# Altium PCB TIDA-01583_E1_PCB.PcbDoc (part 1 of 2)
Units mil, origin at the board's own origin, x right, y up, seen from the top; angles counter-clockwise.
Board outline 2000 x 2400 mil, 4 copper layers (Top Layer, GND, PWR, Bottom Layer), stack 5.6 mil thick; 127 components, 58 nets, 301 pads, 119 vias.
Unrouted connection lines stored in the file: 16.
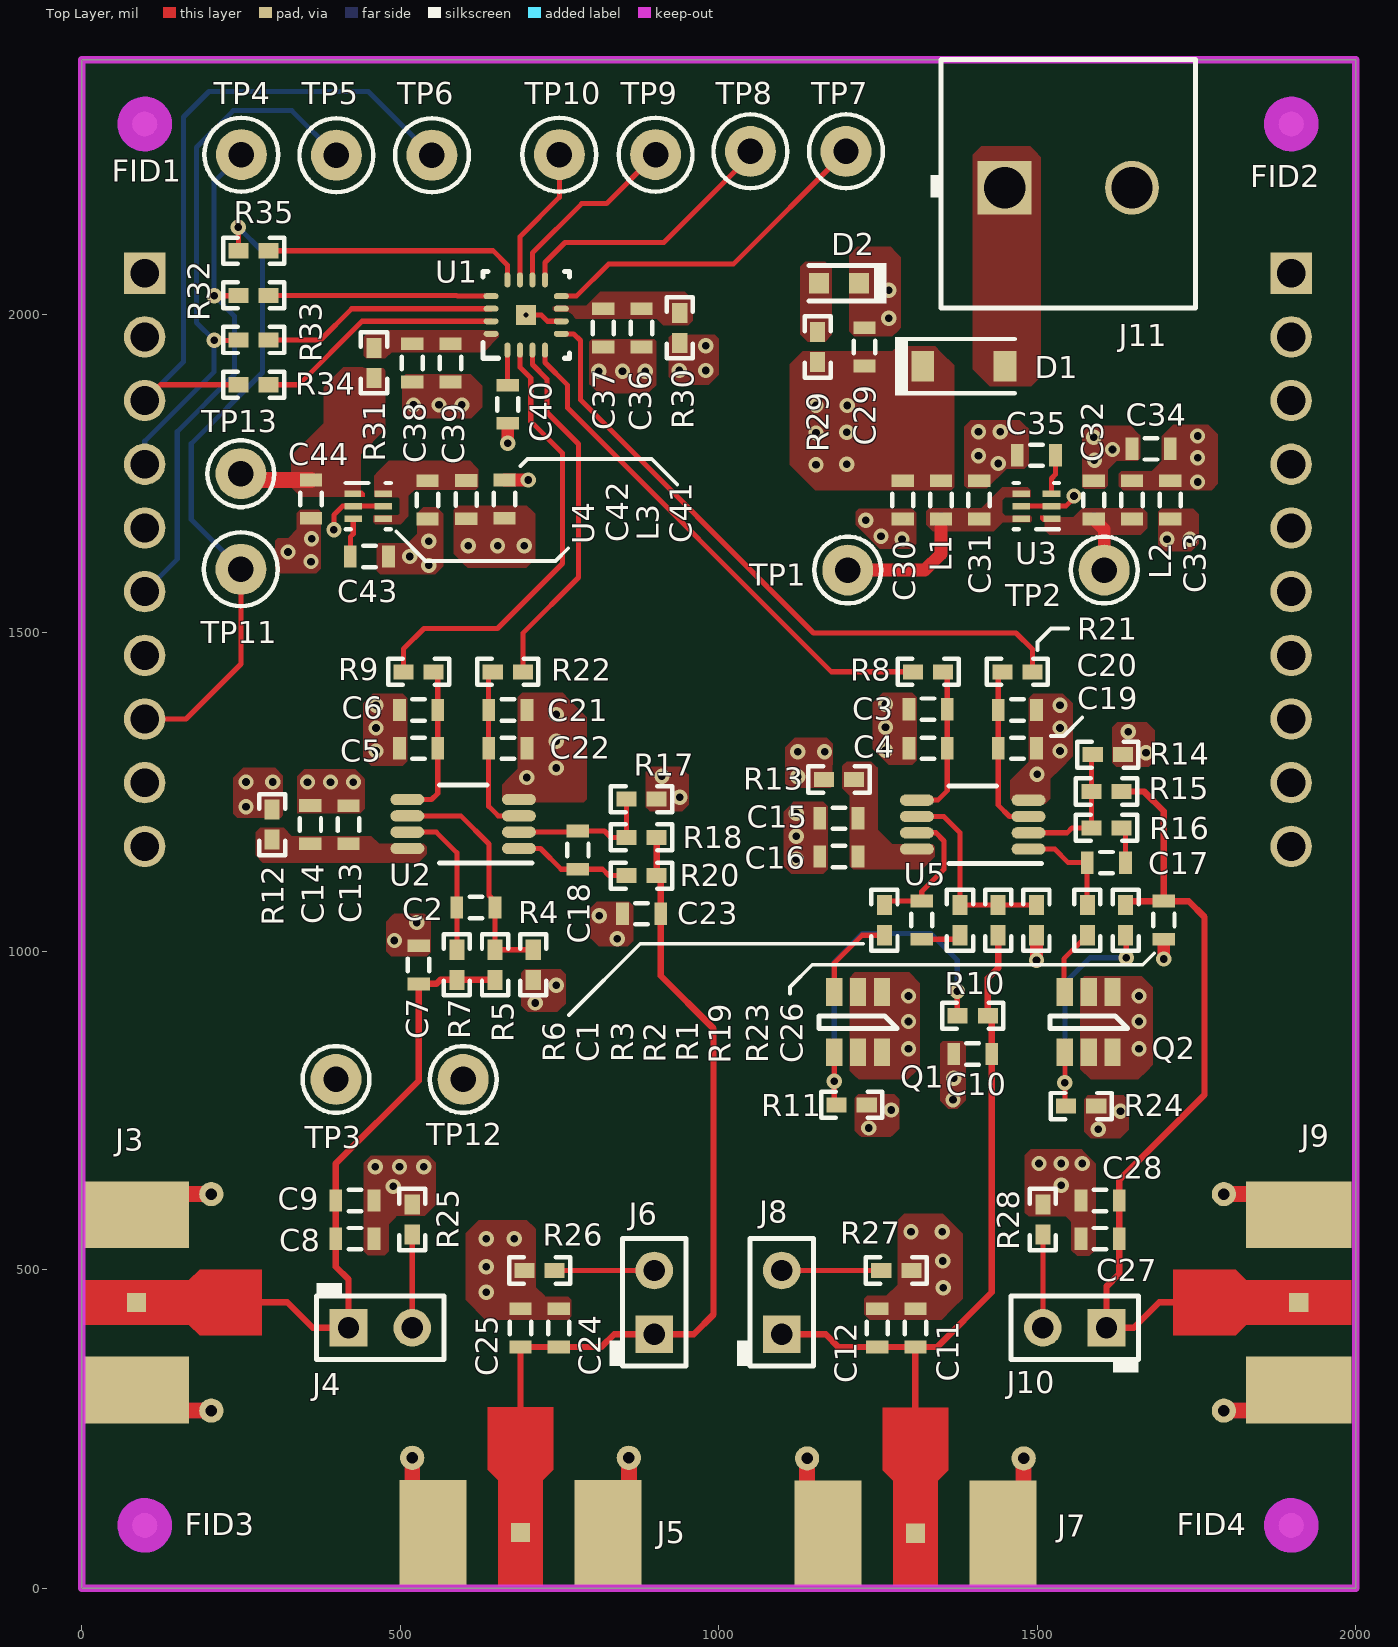
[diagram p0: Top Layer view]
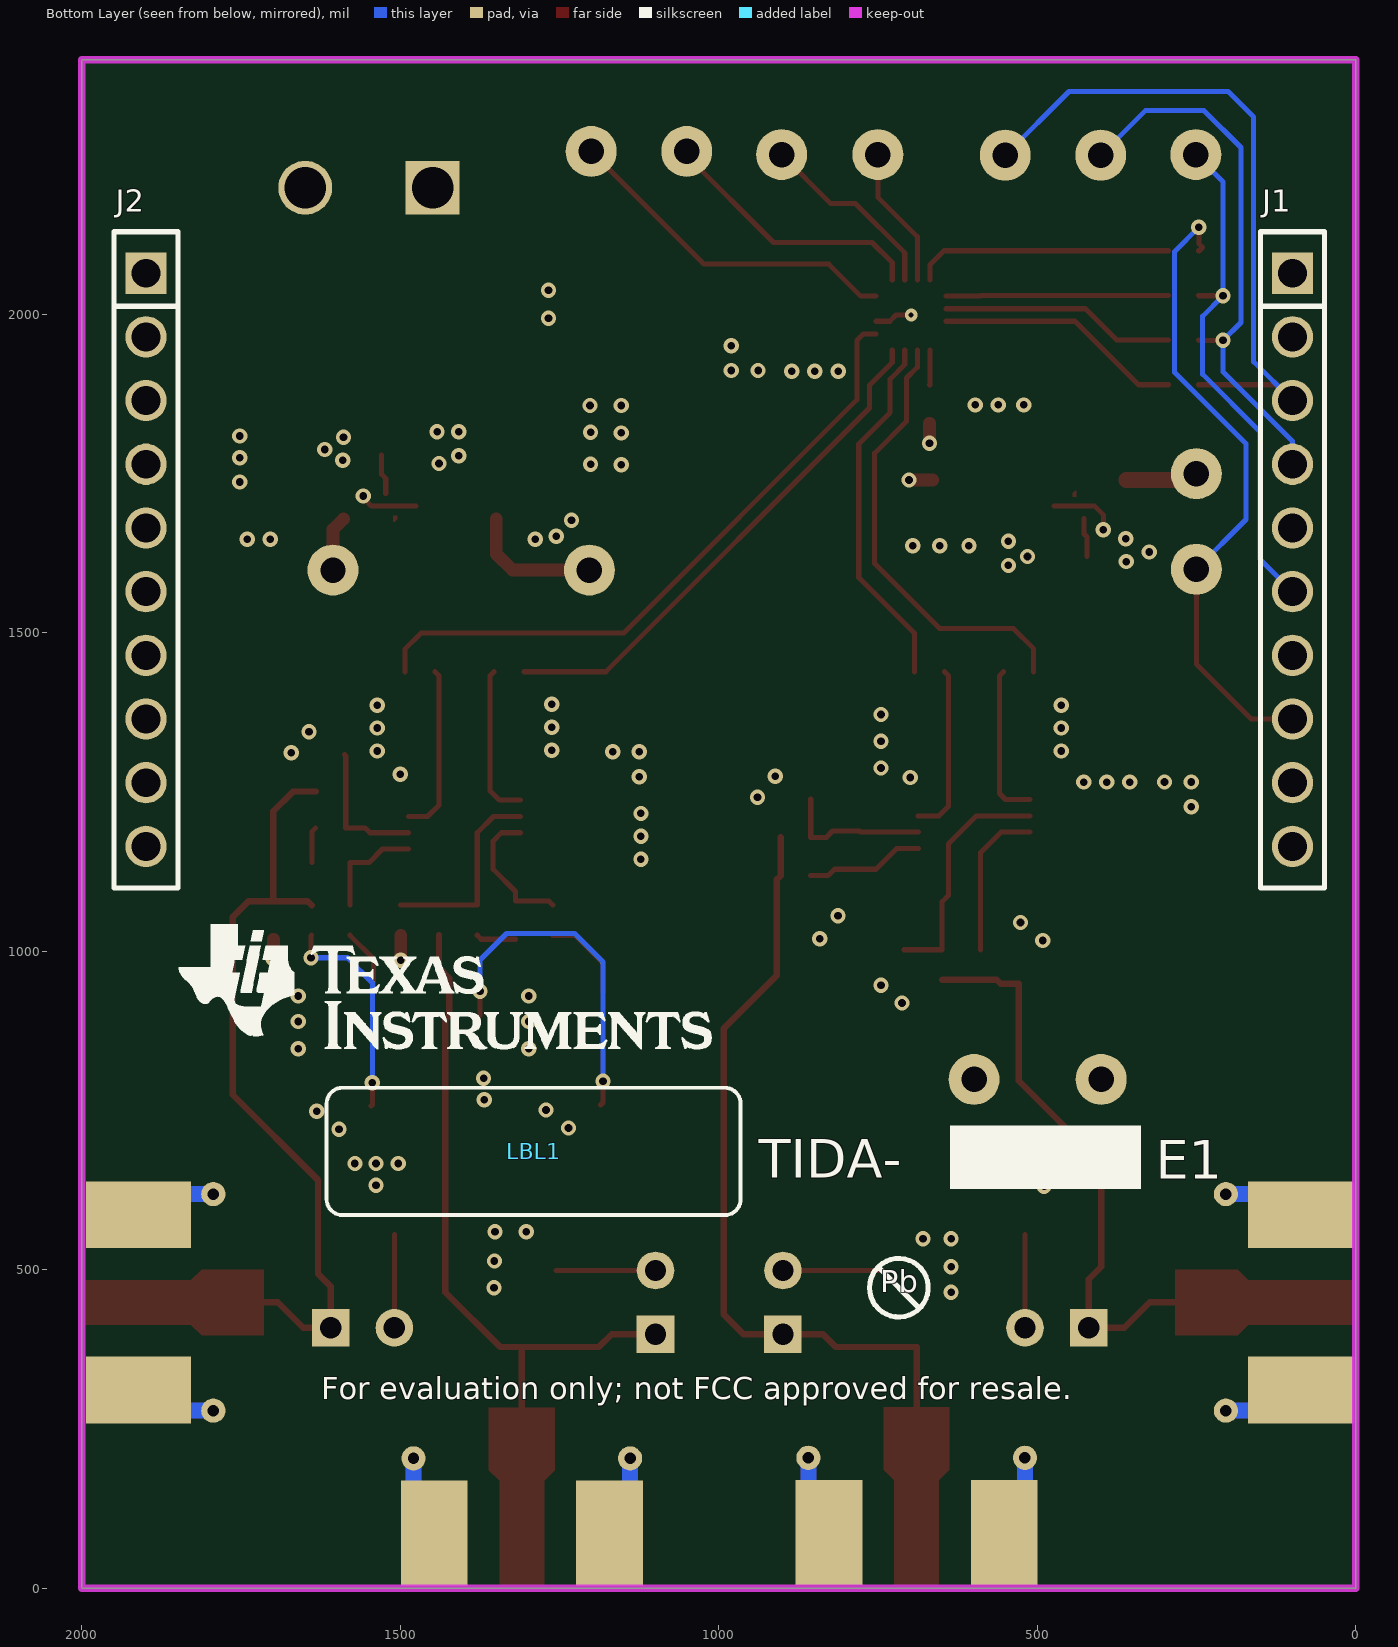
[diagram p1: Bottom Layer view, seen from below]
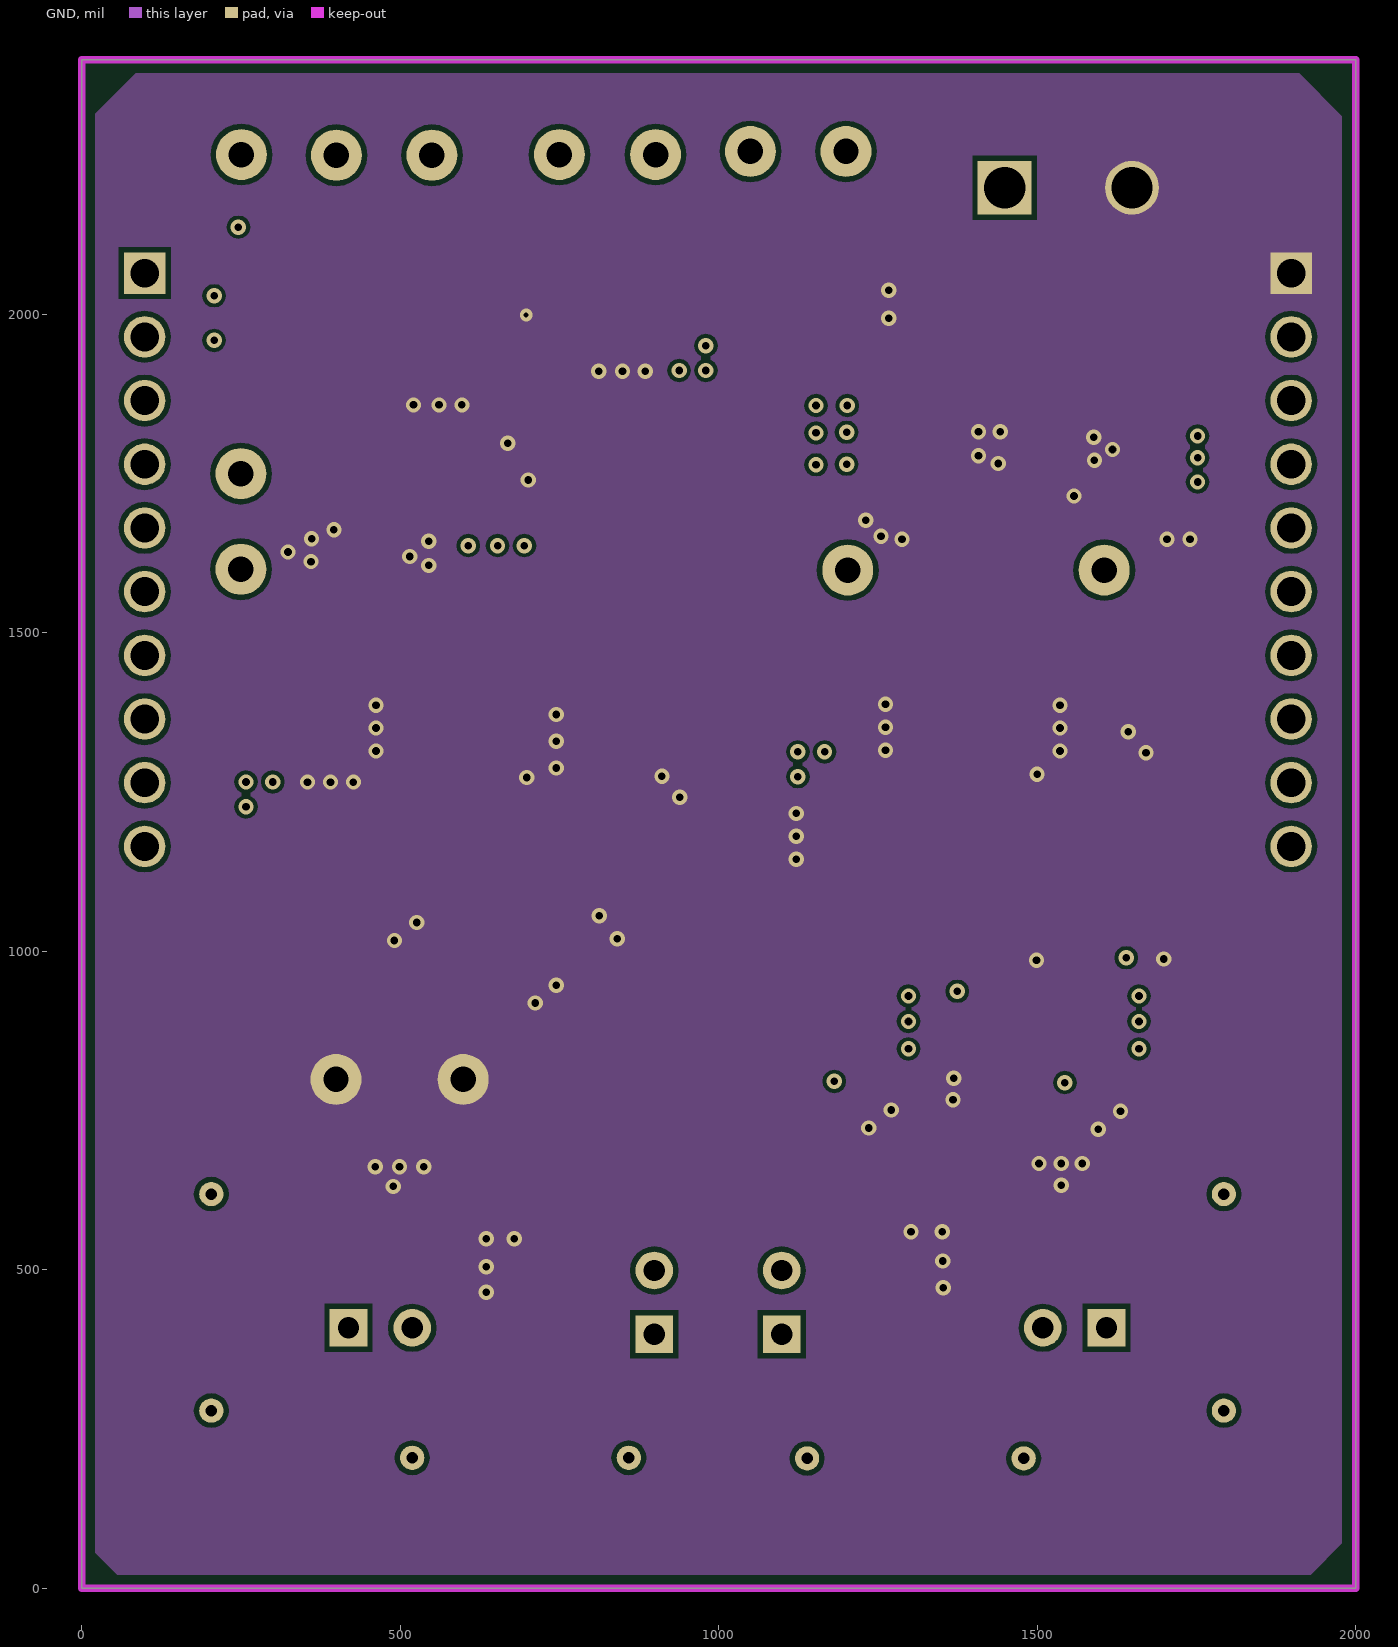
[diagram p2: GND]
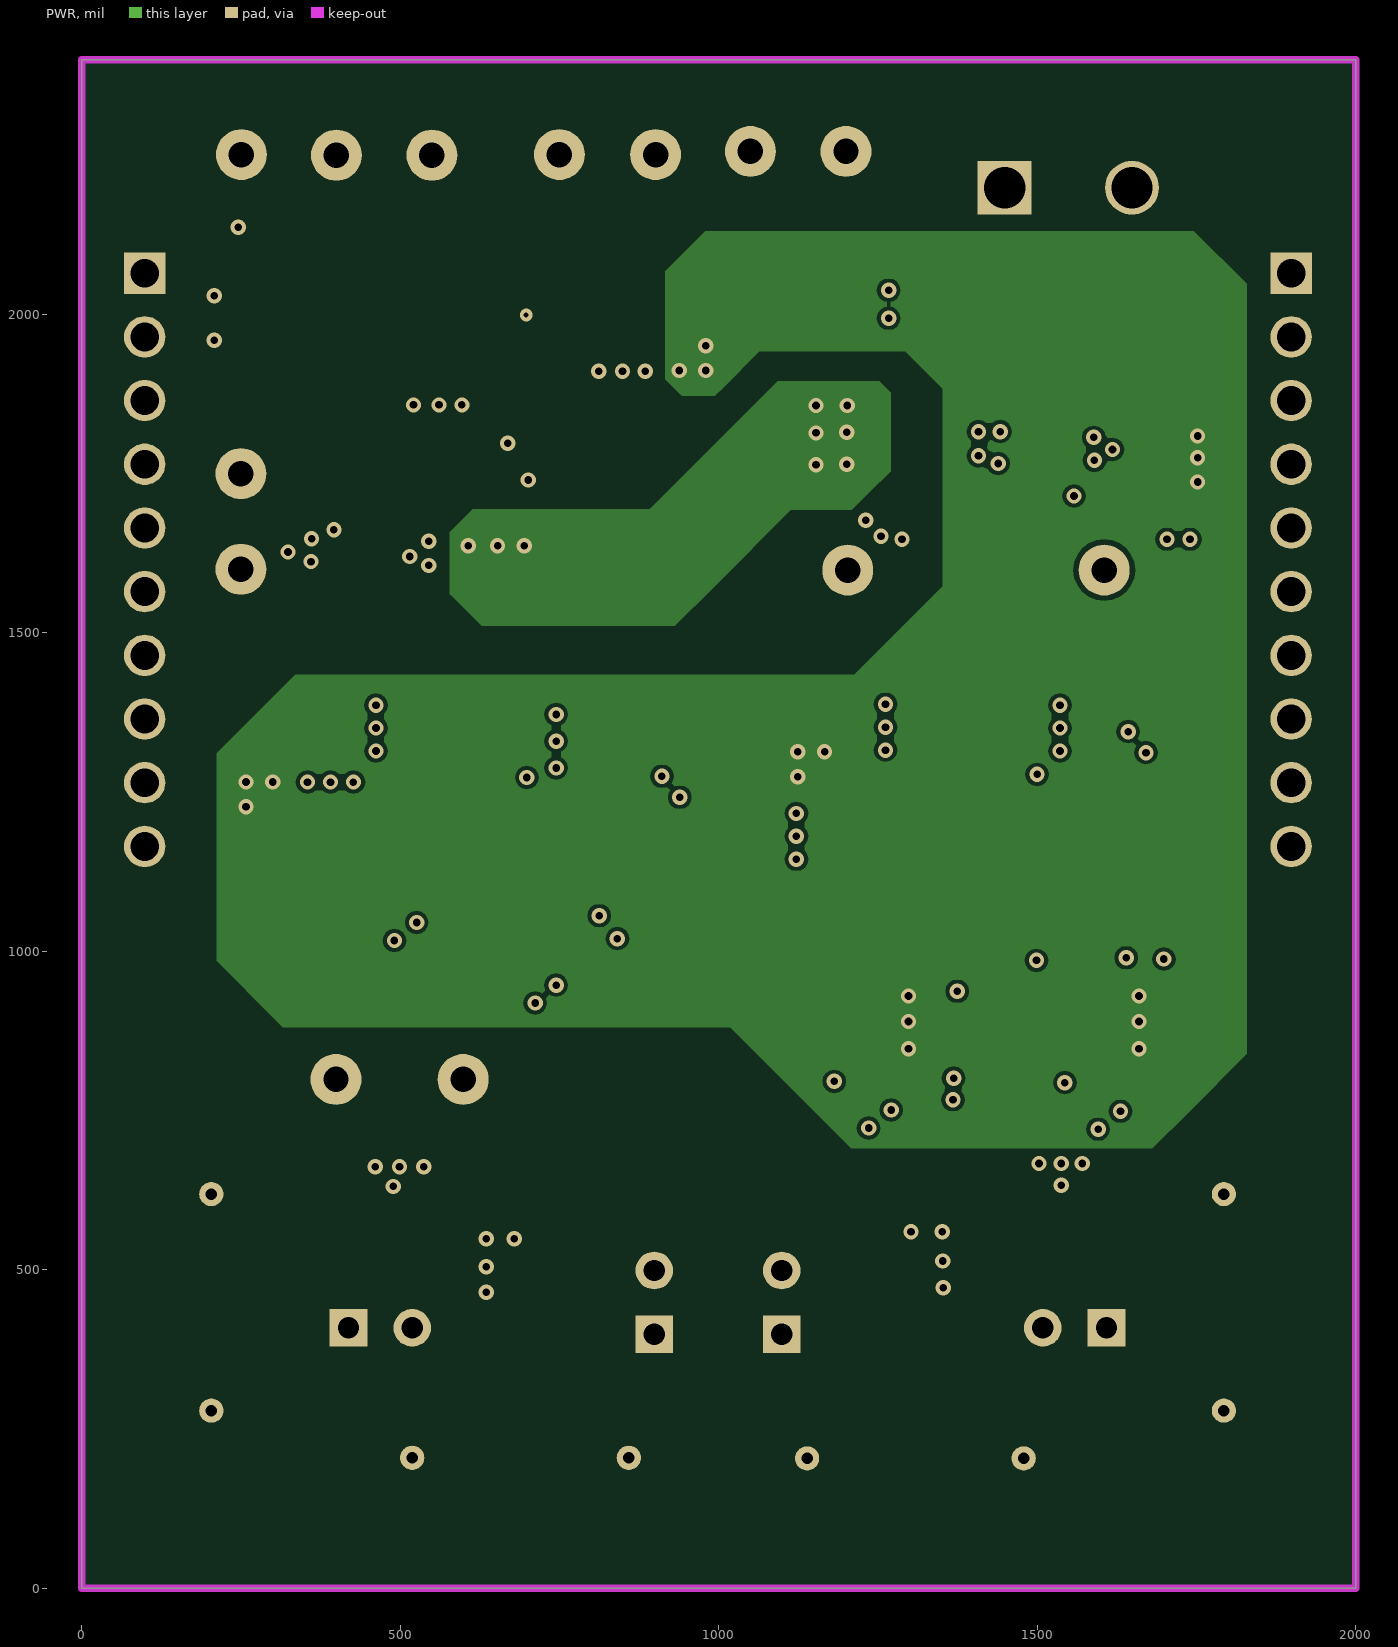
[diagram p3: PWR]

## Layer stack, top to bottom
Top Solder: solder mask 0.4, Solder Resist, Dk 3.5
Top Layer: signal copper 1.4
GND: signal copper 1.4
PWR: signal copper 1.4
Bottom Layer: signal copper 1.4
Bottom Solder: solder mask 0.4, Solder Resist, Dk 3.5

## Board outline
0,0 2000,0 2000,2400 0,2400

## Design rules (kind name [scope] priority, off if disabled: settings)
AcuteAngle [All] p1: minimum=4.50000000000000E+0001 checktracksonly=FALSE
AssemblyTestPointUsage [All] p1: valid=2
Clearance Keepout [iskeepout vs inpoly] p1: gap=15 ignorepadtopadclearanceinfootprint=FALSE except(0: Arc-Hole Track-Hole SMDPad-Hole THPad-Hole Via-Hole Fill-Hole Poly-Hole Region-Hole Text-Hole)
Clearance samenet [isvia vs ispad] p2: gap=6 ignorepadtopadclearanceinfootprint=FALSE except(0: Arc-Hole Track-Hole SMDPad-Hole THPad-Hole Via-Hole Fill-Hole Poly-Hole Region-Hole Text-Hole)
Clearance polygon [inpolygon] p3: gap=12 ignorepadtopadclearanceinfootprint=FALSE except(0: Arc-Hole Track-Hole SMDPad-Hole THPad-Hole Via-Hole Fill-Hole Poly-Hole Region-Hole Text-Hole; 6: Via-Poly; 8: THPad-Poly; 9: Track-Poly SMDPad-Poly; 10: SMDPad-SMDPad; 15: Poly-Poly)
Clearance [All] p4: gap=8 ignorepadtopadclearanceinfootprint=FALSE except(0: Arc-Hole Track-Hole SMDPad-Hole THPad-Hole Via-Hole Fill-Hole Poly-Hole Region-Hole Text-Hole; 7: SMDPad-SMDPad)
ComponentClearance ComponentClearance_Logo [InComponentClass(Logo)] p1 off: gap=50 collisioncheckmode=3 verticalgap=10 showdistances=FALSE
ComponentClearance ComponentClearance_ScrewToNut [(HasFootprint('NY PMS 440 0025 PH')) vs (HasFootprint('Keystone_1902C'))] p2 off: gap=5 collisioncheckmode=3 verticalgap=10 showdistances=FALSE
ComponentClearance ComponentClearance_MountingHoles [InComponentClass('Mounting Holes')] p3 off: gap=250 collisioncheckmode=3 verticalgap=100000 showdistances=FALSE
ComponentClearance ComponentClearance_SmallPassives [HasFootprint('0201*') or HasFootprint('0402*') or HasFootprint('0508') or HasFootprint('0603*') or HasFootprint('0612') or HasFootprint('0805*') or HasFootprint('0815*') or HasFootprint('0830*') or HasFootprint('1206*') or HasFootprint('1210*') or HasFootprint('1808*') or HasFootprint('1812*') or HasFootprint('1825*') or HasFootprint('2010*') or HasFootprint('2220*') or HasFootprint('2225*') or HasFootprint('2512*') or HasFootprint('2728*') or HasFootprint('3518*') vs HasFootprint('0201*') or HasFootprint('0402*') or HasFootprint('0508') or HasFootprint('0603*') or HasFootprint('0612') or HasFootprint('0805*') or HasFootprint('0815*') or HasFootprint('0830*') or HasFootprint('1206*') or HasFootprint('1210*') or HasFootprint('1808*') or HasFootprint('1812*') or HasFootprint('1825*') or HasFootprint('2010*') or HasFootprint('2220*') or HasFootprint('2225*') or HasFootprint('2512*') or HasFootprint('2728*') or HasFootprint('3518*')] p4 off: gap=20 collisioncheckmode=3 verticalgap=10 showdistances=FALSE
ComponentClearance ComponentClearance_THtoSMT [IsThruComponent vs IsSMTComponent] p5 off: gap=100 collisioncheckmode=3 verticalgap=100000 showdistances=FALSE
ComponentClearance ComponentClearance_THtoTH [IsThruComponent vs IsThruComponent] p6 off: gap=118.11 collisioncheckmode=3 verticalgap=100000 showdistances=FALSE
ComponentClearance [All] p7 off: gap=40 collisioncheckmode=3 verticalgap=10 showdistances=FALSE
DiffPairsRouting [All] p1: maxlimit=100 minlimit=10 mostfreqgap=10 toplayer_minwidth=15 toplayer_maxwidth=15 toplayer_prefwidth=15 midlayer1_minwidth=15 midlayer1_maxwidth=15 midlayer1_prefwidth=15 midlayer2_minwidth=15 midlayer2_maxwidth=15 midlayer2_prefwidth=15 bottomlayer_minwidth=15 bottomlayer_maxwidth=15 bottomlayer_prefwidth=15 maxuncoupledlength=1000
FabricationTestPointUsage TestPointUsage [All] p1: valid=2 allowmultiple=FALSE
FabricationTestpoint Testpoint [All] p1: side=3 testpointundercomponent=TRUE minsize=40 maxsize=100 preferedsize=60 minholesize=0 maxholesize=40 preferedholesize=32 testpointgrid=1 allowsidetop=TRUE allowsidebottom=TRUE usegrid=TRUE gridtolerance=0.01
FanoutControl Fanout_LCC [IsLCC] p1: bgadir=Out bgaviamode=Centered fanoutstyle=Auto fanoutdirection=Alternating viagrid=1 // Fanout_LCC (Default Rule)
FanoutControl Fanout_BGA [IsBGA] p2: bgadir=Out bgaviamode=Centered fanoutstyle=Auto fanoutdirection=Alternating viagrid=1 // Fanout_BGA (Default Rule)
FanoutControl Fanout_Default [All] p4: bgadir=Out bgaviamode=Centered fanoutstyle=Auto fanoutdirection=Alternating viagrid=1 // Fanout_Default (Default Rule)
FanoutControl Fanout_Small [(CompPinCount < 5)] p5: bgadir=Out bgaviamode=Centered fanoutstyle=Auto fanoutdirection=OutThenIn viagrid=1 // Fanout_Small (Default Rule)
HoleSize [All] p1: absolutevalues=TRUE maxlimit=251 minlimit=8 maxpercent=80.000 minpercent=20.000
MinimumAnnularRing [All] p1: minimumring=9
MinimumSolderMaskSliver MinimumSolderMaskSliver_Logo [InComponentClass('Logo') vs InComponentClass('Logo')] p1: minsoldermaskwidth=0.7
MinimumSolderMaskSliver [All] p2: minsoldermaskwidth=4
PolygonConnect [All] p1: connectstyle=Direct reliefconductorwidth=10 reliefentries=4 polygonreliefangle="90 Angle" airgapwidth=10
RoutingVias [All] p1: holewidth=25 width=40 viastyle="Through Hole" minholewidth=28 minwidth=50 maxholewidth=28 maxwidth=50
SMDToCorner [All] p1: distance=30000
SilkToSilkClearance [All] p1: silktosilkclearance=5
SilkToSolderMaskClearance SilkscreenOverComponentPads [IsPad] p1: minsilkscreentomaskgap=5 clearancetoexposedcopper=TRUE
SolderMaskExpansion [All] p1: expansion=3
Width PWR [InNetClass('PWR')] p1: maxlimit=100 minlimit=8 preferedwidth=20
Width [All] p2: maxlimit=100 minlimit=8 preferedwidth=8
17 further rules are at their usual default settings.

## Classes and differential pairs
component class TIDA-01583_E1_Sheet-2: C1 C2 C3 C4 C5 C6 C7 C8 C9 C10 C11 C12 C13 C14 C15 C16 C17 C18 C19 C20 C21 C22 C23 C24 C25 C26 C27 C28 Q1 Q2 R1 R2 R3 R4 R5 R6 R7 R8 R9 R10 R11 R12 R13 R14 R15 R16 R17 R18 R19 R20 R21 R22 R23 R24 U2 U5
component class TIDA-01582_E1_Sheet-1: C29 C30 C31 C32 C33 C34 C35 C36 C37 C38 C39 C40 C41 C42 C43 C44 D1 D2 J1 J2 J3 J4 J5 J6 J7 J8 J9 J10 J11 L1 L2 L3 R25 R26 R27 R28 R29 R30 R31 R32 R33 R34 R35 TP1 TP2 TP3 TP4 TP5 TP6 TP7 TP8 TP9 TP10 TP11 TP12 TP13 U1 U3 U4
component class Label: LBL1
component class Logo: Logo1
component class TIDA-01583_E1_TID_Hardware: FID1 FID2 FID3 FID4 LBL1 Logo1 Logo2 Logo3 ZZ1 ZZ2 ZZ3 ZZ4
component class FiducialMark: FID1 FID2 FID3 FID4
component class AssemblyNote: ZZ1 ZZ2 ZZ3 ZZ4
component class Header: J4 J6 J8 J10

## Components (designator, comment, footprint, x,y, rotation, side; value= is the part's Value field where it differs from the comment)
C1 "GRM188R71A684KA61D" 0603S 1319,1048.99 r90 top value=0.68uF
C2 "GRM188R71A564KA61D" 0603S 619,1068.99 r180 top value=0.56uF
C3 "C1608X5R1E106M080AC" 0603S 1329,1380.34 r180 top value=10uF
C4 "C1608X5R1E106M080AC" 0603S 1329,1318.99 r180 top value=10uF
C5 "C1608X5R1E106M080AC" 0603S 529,1318.99 r180 top value=10uF
C6 "C1608X5R1E106M080AC" 0603S 529,1378.99 r180 top value=10uF
C7 "C1608X5R1E106M080AC" 0603S 529,978.99 r90 top value=10uF
C8 "C1608X5R1E106M080AC" 0603S 429,548.99 r0 top value=10uF
C9 "C0603C104J3RACTU" 0603S 429,608.99 r0 top value=0.1uF
C10 "C1608X5R1E106M080AC" 0603S 1399,838.99 r180 top value=10uF
C11 "C1608X5R1E106M080AC" 0603S 1309,408.99 r90 top value=10uF
C12 "C0603C104J3RACTU" 0603S 1249,408.99 r90 top value=0.1uF
C13 "GRM188R61E475KE11D" 0603S 419,1198.84 r90 top value=4.7uF
C14 "C0603C104J3RACTU" 0603S 359,1198.99 r90 top value=0.1uF
C15 "GRM188R61E475KE11D" 0603S 1189,1208.99 r180 top value=4.7uF
C16 "C0603C104J3RACTU" 0603S 1189,1148.99 r180 top value=0.1uF
C17 "GRM188R71A684KA61D" 0603S 1608.69,1139.31 r180 top value=0.68uF
C18 "GRM188R71A564KA61D" 0603S 779,1158.99 r270 top value=0.56uF
C19 "C1608X5R1E106M080AC" 0603S 1469,1318.99 r0 top value=10uF
C20 "C1608X5R1E106M080AC" 0603S 1469,1378.99 r0 top value=10uF
C21 "C1608X5R1E106M080AC" 0603S 669,1378.99 r0 top value=10uF
C22 "C1608X5R1E106M080AC" 0603S 669,1318.99 r0 top value=10uF
C23 "C1608X5R1E106M080AC" 0603S 879,1058.99 r180 top value=10uF
C24 "C1608X5R1E106M080AC" 0603S 749,408.99 r90 top value=10uF
C25 "C0603C104J3RACTU" 0603S 689,408.99 r90 top value=0.1uF
C26 "C1608X5R1E106M080AC" 0603S 1699,1048.99 r270 top value=10uF
C27 "C1608X5R1E106M080AC" 0603S 1599,548.99 r180 top value=10uF
C28 "C0603C104J3RACTU" 0603S 1599,608.99 r180 top value=0.1uF
C29 "GRM188R61E106MA73D" 0603S 1229,1948.99 r90 top value=10uF
C30 "EMK107BB7225KA-T" 0603S 1289,1708.99 r270 top value=2.2uF
C31 "EMK107BB7225KA-T" 0603S 1409,1708.99 r90 top value=2.2uF
C32 "EMK107BB7225KA-T" 0603S 1589,1708.99 r90 top value=2.2uF
C33 "EMK107BB7225KA-T" 0603S 1709,1708.99 r270 top value=2.2uF
C34 "GRM188R61E106MA73D" 0603S 1679,1788.99 r180 top value=10uF
C35 "C0603C104J3RACTU" 0603S 1499,1778.99 r180 top value=0.1uF
C36 "GRM188R61E475KE11D" 0603S 879,1978.99 r270 top value=4.7uF
C37 "C0603C104J3RACTU" 0603S 819,1978.99 r270 top value=0.1uF
C38 "GRM188R61E475KE11D" 0603S 519,1923.99 r270 top value=4.7uF
C39 "C0603C104J3RACTU" 0603S 579,1923.99 r270 top value=0.1uF
C40 "C0603C104J3RACTU" 0603S 669,1858.99 r270 top value=0.1uF
C41 "EMK107BB7225KA-T" 0603S 663.81,1710 r90 top value=2.2uF
C42 "EMK107BB7225KA-T" 0603S 542.96,1708.99 r270 top value=2.2uF
C43 "C0603C104J3RACTU" 0603S 451.82,1620 r0 top value=0.1uF
C44 "GRM188R61E106MA73D" 0603S 360,1710 r270 top value=10uF
D1 "MBR0540T1G" SOD-123 1385,1918.99 r0 top value=40V
D2 "150060RS75000" WL-SMCW_RED 1189,2048.99 r180 top value=Red
FID1 "Fiducial" Fiducial10-20 99,2298.99 r0 top
FID2 "Fiducial" Fiducial10-20 1899,2298.99 r0 top
FID3 "Fiducial" Fiducial10-20 99,98.87 r0 top
FID4 "Fiducial" Fiducial10-20 1899,98.87 r0 top
J1 "SSW-110-23-F-S" CONN_SSW-110-23-F-S 99,2064.81 r90 bottom locked
J2 "SSW-110-23-F-S" CONN_SSW-110-23-F-S 1899,2064.81 r90 bottom locked
J3 "142-0711-821" Johnson_142-0711-821 3.5,448.99 r90 top locked
J4 "800-10-002-10-001000" Mill-Max_800-10-002-10-001000 469,408.99 r0 top
J5 "142-0711-821" Johnson_142-0711-821 689,4.99 r180 top locked
J6 "800-10-002-10-001000" Mill-Max_800-10-002-10-001000 899,448.99 r90 top
J7 "142-0711-821" Johnson_142-0711-821 1309,3.99 r180 top locked
J8 "800-10-002-10-001000" Mill-Max_800-10-002-10-001000 1099,448.99 r90 top
J9 "142-0711-821" Johnson_142-0711-821 1993.36,448.99 r270 top locked
J10 "800-10-002-10-001000" Mill-Max_800-10-002-10-001000 1559,408.99 r180 top
J11 "039544-3002" Molex_039544-3002 1549,2198.99 r0 top locked
L1 "MMZ1608R150ATA00" 0603S 1349,1708.99 r270 top value="15 ohm"
L2 "MMZ1608R150ATA00" 0603S 1649,1708.99 r90 top value="15 ohm"
L3 "MMZ1608R150ATA00" 0603S 603.81,1709.15 r90 top value="15 ohm"
LBL1 "Size: 0.65\" x 0.20 \"" Label_650x200 1290.44,685.99 r0 bottom locked
Logo1 "Texas Instruments" TI_Stacked_Overlay_Small -3165.07,-1127.73 r180 bottom
Logo2 "Pb-Free Symbol" Pb-Free_Overlay_Small -3877,-1600.01 r180 bottom
Logo3 "FCC disclaimer" FCC_disclaimer -3619.64,-2025.67 r180 bottom
Q1 "ZXT10N50DE6" SOT-23-6 1219,888.99 r270 top value="50 V"
Q2 "ZXT10N50DE6" SOT-23-6 1580.97,888.99 r270 top value="50 V"
R1 "CRCW04027K50FKED" 0402 1499,1048.99 r90 top value=7.50k
R2 "CRCW04027K50FKED" 0402 1439,1048.99 r270 top value=7.50k
R3 "ERJ-2GE0R00X" 0402 1379,1048.99 r90 top value=0
R4 "CRCW04027K50FKED" 0402 709,978.99 r90 top value=7.50k
R5 "CRCW04027K50FKED" 0402 649,978.99 r270 top value=7.50k
R6 "ERJ-2GEJ470X" 0402 1260.34,1048.99 r270 top value=47
R7 "ERJ-2GEJ470X" 0402 589,978.99 r270 top value=47
R8 "CRCW04027K50FKED" 0402 1329,1438.99 r0 top value=7.50k
R9 "CRCW04027K50FKED" 0402 529,1438.99 r0 top value=7.50k
R10 "CRCW040210R0FKED" 0402 1399,898.99 r0 top value=10.0
R11 "MCR01MRTF1002" 0402 1209,758.99 r0 top value=10.0k
R12 "CRCW040210R0FKED" 0402 299,1198.99 r270 top value=10.0
R13 "CRCW040210R0FKED" 0402 1189,1269.86 r0 top value=10.0
R14 "CRCW04027K50FKED" 0402 1611,1308.99 r180 top value=7.50k
R15 "CRCW04027K50FKED" 0402 1609,1251.02 r0 top value=7.50k
R16 "ERJ-2GE0R00X" 0402 1609,1193.99 r180 top value=0
R17 "CRCW04027K50FKED" 0402 879,1238.99 r180 top value=7.50k
R18 "CRCW04027K50FKED" 0402 879,1178.99 r0 top value=7.50k
R19 "ERJ-2GEJ470X" 0402 1579,1048.99 r270 top value=47
R20 "ERJ-2GEJ470X" 0402 879,1118.99 r0 top value=47
R21 "CRCW04027K50FKED" 0402 1469,1438.99 r180 top value=7.50k
R22 "CRCW04027K50FKED" 0402 669,1438.99 r180 top value=7.50k
R23 "CRCW040210R0FKED" 0402 1639,1048.99 r90 top value=10.0
R24 "MCR01MRTF1002" 0402 1569.32,757.18 r0 top value=10.0k
R25 "CRCW04021K00FKED" 0402 519,578.99 r270 top value=1.00k
R26 "CRCW04021K00FKED" 0402 719,498.99 r0 top value=1.00k
R27 "CRCW0402120RJNED" 0402 1279,498.99 r180 top value=120
R28 "CRCW0402120RJNED" 0402 1509,578.99 r270 top value=120
R29 "CRCW04021K00FKED" 0402 1155.54,1948.84 r90 top value=1.00k
R30 "CRCW040210R0FKED" 0402 939,1978.99 r90 top value=10.0
R31 "CRCW040210R0FKED" 0402 459,1923.99 r90 top value=10.0
R32 "CRCW040210R0FKED" 0402 270,2030 r0 top value=10.0
R33 "CRCW040210R0FKED" 0402 270,1960 r0 top value=10.0
R34 "CRCW040210R0FKED" 0402 270,1889.64 r0 top value=10.0
R35 "CRCW040210R0FKED" 0402 270,2100 r0 top value=10.0
TP1 "5000" Keystone5000 1202.78,1598.69 r0 top
TP2 "5000" Keystone5000 1605.41,1598.69 r0 top locked
TP3 "5001" Keystone5001 399.32,798.99 r0 top
TP4 "5000" Keystone5000 250.76,2250.99 r0 top
TP5 "5000" Keystone5000 400,2250 r0 top
TP6 "5000" Keystone5000 550,2250 r0 top
TP7 "5003" Keystone5003 1200,2255.99 r0 top
TP8 "5003" Keystone5003 1050,2255.99 r0 top
TP9 "5003" Keystone5003 901,2250.99 r0 top
TP10 "5003" Keystone5003 750,2250.99 r0 top
TP11 "5000" Keystone5000 250,1600 r90 top
TP12 "5001" Keystone5001 599,798.99 r0 top
TP13 "5000" Keystone5000 250,1750 r90 top
U1 "DAC80508ZRTET" RTE0016D 697.88,1999.15 r90 top
U2 "OPA2192IDGKR" DGK0008A_N 599,1199.99 r180 top locked
U3 "TPS71750DSET" DSE0006A 1499,1698.99 r180 top locked
U4 "TPS71733DSET" DSE0006A 450,1698.99 r0 top
U5 "OPA2192IDGKR" DGK0008A_N 1399,1198.99 r180 top locked
ZZ1 "This Assembly Note is for PCB labels only" AssemblyNoteLabel 33,3198.25 r0 top
ZZ2 "These assemblies are ESD sensitive, ESD precautions shall be observed." AssemblyNote 28,3087.37 r0 top
ZZ3 "These assemblies must be clean and free from flux and all contaminants. Use of no clean flux is not acceptable." AssemblyNote 28,2998.81 r0 top
ZZ4 "These assemblies must comply with workmanship standards IPC-A-610 Class 2, unless otherwise specified." AssemblyNote 28,2910.25 r0 top

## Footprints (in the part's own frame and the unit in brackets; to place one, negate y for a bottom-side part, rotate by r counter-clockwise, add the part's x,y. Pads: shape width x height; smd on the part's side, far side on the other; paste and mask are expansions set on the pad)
0402 [mm] "0402 from SM-752 data"
  rect 0.8x0.6 smd: 1(-0.6,0) 2(0.6,0)
  silkscreen extent -1.22,-0.52 1.22,0.52, body extent -0.55,-0.3 0.55,0.3, height 0.6
0603S [mil]
  rect 20x35 smd: 1(-30,0) 2(30,0)
  silkscreen extent -10,-17 10,17, body extent -34,-19 34,19, height 39
AssemblyNote [mil] "Assembly Note"
AssemblyNoteLabel [mil] "Assembly Note for PCB Labels"
CONN_SSW-110-23-F-S [mm] "SAMTEC"
  rect 1.65x1.65 hole 1.15: 1(0,0)
  round 1.65 hole 1.15: 2(-2.54,0) 3(-5.08,0) 4(-7.62,0) 5(-10.16,0) 6(-12.7,0) 7(-15.24,0) 8(-17.78,0) 9(-20.32,0) 10(-22.86,0)
  silkscreen extent -24.51,-1.27 1.65,1.27, body extent -24.43,-1.27 1.57,1.27, height 8.59
DGK0008A_N [mm] "TSOP, 8-Leads, Body 3x3mm, Pitch 0.65mm, IPC Medium Density"
  oval 1.35x0.45 smd: 1(-2.225,0.975) 2(-2.225,0.325) 3(-2.225,-0.325) 4(-2.225,-0.975) 5(2.225,-0.975) 6(2.225,-0.325) 7(2.225,0.325) 8(2.225,0.975)
  silkscreen extent -2.75,-1.55 0.95,1.55, body extent -2.45,-1.5 2.45,1.5, height 0.96
DSE0006A [mm] "TI recommended land pattern"
  rect 0.66x0.25 smd: 1(-0.62,0.5)
  rect 0.7x0.25 smd: 2(-0.6,0) 3(-0.6,-0.5) 4(0.6,-0.5) 5(0.6,0) 6(0.6,0.5)
  Top Layer region: -0.3,0.625 -0.25,0.625 -0.15,0.525 -0.15,0.375 -0.3,0.375
  silkscreen extent -0.9,-0.92 0.9,0.92, body extent -0.77,-0.77 0.77,0.77, height 0.8
FCC_disclaimer [mil]
Fiducial10-20 [mm]
  round 1 smd mask+0.5: 1(0,0)
  Top Layer keep-out circle w1.178: c0,0 r0.5
Johnson_142-0711-821 [mil] "SMA JACK EDGE MNT, SMT"
  rect 30x30 smd: 1(0,-82.5)
  rect 105x165 smd: 2(-137.5,-82.5) 3(137.5,-82.5)
  rect 105x165 smd far side: 4(-137.5,-82.5) 5(137.5,-82.5)
  round 38 hole 18: ""(-170,-200) ""(170,-200)
  Top Layer region: -51.5,-279.35 -51.5,-181.5 -35,-165 -35,0 35,0 35,-165 51.5,-181.5 51.5,-279.35
  body extent -125,-150 125,375, height 140
Keystone5000 [mil] "For Keystone 500x miniature loop terminals"
  round 80 hole 40: 1(0,0)
  silkscreen extent -52,-52 52,52, body extent -49,-49 49,49, height 182
Keystone5001 [mil] "For Keystone 500x miniature loop terminals"
  round 80 hole 40: 1(0,0)
  silkscreen extent -52,-52 52,52, body extent -49,-49 49,49, height 182
Keystone5003 [mil] "For Keystone 500x miniature loop terminals"
  round 80 hole 40: 1(0,0)
  silkscreen extent -58,-58 58,58, body extent -49,-49 49,49, height 182
Label_650x200 [mil] "Thermal Transfer Label"
  round 1 on Mech14: 0(0,0)
  silkscreen extent -325,-100 325,100, body extent -325,-100 325,100, height 1
Mill-Max_800-10-002-10-001000 [mm] "Mill-Max"
  rect 1.5x1.5 hole 0.85: 1(-1.27,0)
  round 1.5 hole 0.85: 2(1.27,0)
  silkscreen extent -2.54,-1.27 2.54,1.78, body extent -2.54,-1.27 2.54,1.27, height 8.13
Molex_039544-3002 [mm] "Terminal Block, 5.08mm, 2x1, TH"
  rect 2.15x2.15 hole 1.65: 1(-2.54,0)
  round 2.15 hole 1.65: 2(2.54,0)
  silkscreen extent -5.5,-4.8 5.08,5.11, body extent -5.08,-4.8 5.08,5.11, height 14.48
Pb-Free_Overlay_Small [mil]
  silkscreen extent -4640,2026 -4548,2118
RTE0016D [mm] "QFN, 16-Leads, Body 3x3mm, Pitch 0.5mm"
  oval 0.6x0.24 smd: 1(-1.4,0.75) 2(-1.4,0.25) 3(-1.4,-0.25) 4(-1.4,-0.75) 9(1.4,-0.75) 10(1.4,-0.25) 11(1.4,0.25) 12(1.4,0.75)
  oval 0.24x0.6 smd: 5(-0.75,-1.4) 6(-0.25,-1.4) 7(0.25,-1.4) 8(0.75,-1.4) 13(0.75,1.4) 14(0.25,1.4) 15(-0.25,1.4) 16(-0.75,1.4)
  rect 0.8x0.8 smd paste-0.85: 17(0,0)
  silkscreen extent -1.72,-1.73 1.72,1.73, body extent -1.57,-1.57 1.58,1.58, height 0.81
SOD-123 [mm] "On Semi recommended land pattern"
  rect 0.915x1.22 smd: 1(-1.637,0) 2(1.637,0)
  silkscreen extent -2.74,-1.17 2.03,1.17, body extent -1.93,-0.9 1.93,0.9, height 1.35
SOT-23-6 [mm] "SOT23, 6-Leads, Body 3.0x1.7mm, Pitch 0.95mm, Lead Span 2.9mm, IPC Medium Density"
  rect 1.1x0.65 smd: 1(-1.2,0.95) 2(-1.2,0) 3(-1.2,-0.95) 4(1.2,-0.95) 5(1.2,0) 6(1.2,0.95)
  silkscreen extent -0.25,-1.55 0.25,1.55, body extent -1.5,-1.5 1.5,1.5, height 1.3
TI_Stacked_Overlay_Small [mil]
  silkscreen extent -5012,1974 -4176,2170
WL-SMCW_RED [mm] "WURTH"
  rect 0.8x0.8 smd: 1(-0.8,0) 2(0.8,0)
  silkscreen extent -1.9,-0.8 1.2,0.8, body extent -0.85,-0.45 0.85,0.45, height 0.8

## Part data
C1 C17: "CAP, CERM, 0.68 µF, 10 V,+/- 10%, X7R, 0603", Cap_Case=0603, Manufacturer=MuRata, Supplier Part Number 1=GRM188R71A684KA61D-ND, TempCo=X7R, Tolerance_%=10, Value2=10V, ValueDisplayed=0.68µF
C2 C18: "CAP, CERM, 0.56 µF, 10 V,+/- 10%, X7R, 0603", Cap_Case=0603, Manufacturer=MuRata, Supplier Part Number 1=GRM188R71A564KA61D-ND, TempCo=X7R, Tolerance_%=10, Value2=10V, ValueDisplayed=0.56µF
C3 C4 C5 C6 C7 C8 C10 C11 C19 C20 C21 C22 C23 C24 C26 C27: "CAP, CERM, 10 µF, 25 V, +/- 20%, X5R, 0603", Cap_Case=0603, Manufacturer=TDK, Supplier Part Number 1=445-9015-1-ND, TempCo=X5R, Tolerance_%=20, Value1="0.004639 ohm", Value2=25V, ValueDisplayed=10µF
C9 C12 C14 C16 C25 C28 C35 C37 C39 C40 C43: "CAP, CERM, 0.1 µF, 25 V, +/- 5%, X7R, 0603", Cap_Case=0603, Manufacturer=Kemet, Supplier Part Number 1=399-1282-1-ND, TempCo=X7R, Tolerance_%=5, Value1=Unknown, Value2=25V, ValueDisplayed=0.1µF
C13 C15 C36 C38: "CAP, CERM, 4.7 µF, 25 V, +/- 10%, X5R, 0603", Cap_Case=0603, Manufacturer=MuRata, Supplier Part Number 1=490-7203-1-ND, TempCo=X5R, Tolerance_%=10, Value1=Unknown, Value2=25V, ValueDisplayed=4.7µF
C29 C34 C44: "CAP, CERM, 10 µF, 25 V, +/- 20%, X5R, 0603", Cap_Case=0603, Manufacturer=MuRata, Supplier Part Number 1=490-7202-1-ND, TempCo=X5R, Tolerance_%=20, Value1=Unknown, Value2=25V, ValueDisplayed=10µF
C30 C31 C32 C33 C41 C42: "CAP, CERM, 2.2 µF, 16 V, +/- 10%, X7R, 0603", Cap_Case=0603, Manufacturer="Taiyo Yuden", Supplier Part Number 1=EMK107BB7225KA-T-ND, TempCo=X7R, Tolerance_%=10, Value1=Unknown, Value2=16V, ValueDisplayed=2.2µF
D1: "Diode, Schottky, 40V, 0.5A, SOD-123", Manufacturer="ON Semiconductor", Supplier Part Number 1=MBR0540T1GOSCT-ND, Value1=0.5A, Value2=0.51V
D2: "LED, Red, SMD", Color=Red, Manufacturer="Wurth Elektronik", Power_TotalModule=0.072, Supplier Part Number 1=732-4978-1-ND, Value1=0.072W, Value2=2V
FID1 FID2 FID3 FID4: "Fiducial mark.  There is nothing to buy or mount.", Manufacturer=N/A
J1 J2: "Connector, Receptacle, 100mil, 10x1, Gold plated, TH", Manufacturer="Samtec, Inc."
J3 J5 J7 J9: "SMA JACK 50 OHM EDGE MNT, SMT", Color=Gold, Manufacturer="Cinch Connectivity", Supplier Part Number 1=J629-ND
J4 J6 J8 J10: "Header, 100mil, 2x1, TH", Manufacturer=Mill-Max, Supplier Part Number 1=ED7202-ND
J11: "Terminal Block, 5.08mm, 2x1, TH", Color=Black, Current_A=15, Manufacturer=Molex, Supplier Part Number 1=WM7853-ND, Voltage_V=300
L1 L2 L3: "Ferrite Bead, 15 ohm @ 100 MHz, 1.5 A, 0603", Manufacturer=TDK, Supplier Part Number 1=445-2180-1-ND, Value1="0.05 ohm", Value2=1.5A, ValueDisplayed="15 ohm"
LBL1: library part THT-14-423-10, "Thermal Transfer Printable Labels, 0.650\" W x 0.200\" H - 10,000 per roll", Alternate Manufacturer=-, Manufacturer=Brady, Supplier Part Number 1=2065596
Logo1: library part TI_Logo, "Texas Instrument Corporate Signature"
Logo2: library part Pb-Free
Logo3: library part FCC_disclaimer, "FCC_disclaimer"
Q1 Q2: library part "ZXT10N50DE6, Zetex", "Transistor, NPN, 50 V, 3 A, SOT-23-6", Manufacturer=Zetex, Supplier Part Number 1=ZXT10N50DE6TACT-ND, Value1="3 A", Value2=225
R1 R2 R4 R5 R8 R9 R14 R15 R17 R18 R21 R22: "RES, 7.50 k, 1%, 0.063 W, 0402", Manufacturer=Vishay-Dale, Power_W=0.063, Supplier Part Number 1=541-7.50KLCT-ND, TempCo="100 ppm/C", Tolerance_%=1, Value1=1%, Value2=0.063W, Value_Code=7k50, ValueDisplayed=7.50k
R3 R16: "RES, 0, 5%, 0.063 W, 0402", Manufacturer=Panasonic, Power_W=0.063, Supplier Part Number 1=P0.0JCT-ND, TempCo="600 ppm/C", Tolerance_%=5, Value1=5%, Value2=0.063W, Value_Code=0000, ValueDisplayed=0
R6 R7 R19 R20: "RES, 47, 5%, 0.1 W, AEC-Q200 Grade 0, 0402", Manufacturer=Panasonic, Power_W=0.1, Supplier Part Number 1=P47JCT-ND, TempCo="200 ppm/C", Tolerance_%=5, Value1=5%, Value2=0.1W, Value_Code=47R0, ValueDisplayed=47
R10 R12 R13 R23 R30 R31 R32 R33 R34 R35: "RES, 10.0, 1%, 0.063 W, 0402", Manufacturer=Vishay-Dale, Power_W=0.063, Supplier Part Number 1=541-10.0LCT-ND, TempCo="100 ppm/C", Tolerance_%=1, Value1=1%, Value2=0.063W, Value_Code=10R0, ValueDisplayed=10.0
R11 R24: "RES, 10.0 k, 0.1%, 0.063 W, 0402", Manufacturer=Rohm, Power_W=0.063, Supplier Part Number 1=RHM10.0KCDCT-ND, TempCo="100 ppm/C", Tolerance_%=0.1, Value1=0.1%, Value2=0.063W, Value_Code=10k0, ValueDisplayed=10.0k
R25 R26 R29: "RES, 1.00 k, 1%, 0.063 W, 0402", Manufacturer=Vishay-Dale, Power_W=0.063, Supplier Part Number 1=541-1.00KLCT-ND, TempCo="100 ppm/C", Tolerance_%=1, Value1=1%, Value2=0.063W, Value_Code=1k00, ValueDisplayed=1.00k
R27 R28: "RES, 120, 5%, 0.063 W, 0402", Manufacturer=Vishay-Dale, Power_W=0.063, Supplier Part Number 1=541-120JCT-ND, TempCo="200 ppm/C", Tolerance_%=5, Value1=5%, Value2=0.063W, Value_Code=120R, ValueDisplayed=120
TP1 TP2 TP4 TP5 TP6 TP11 TP13: "Test Point, Miniature, Red, TH", Color=Red, Manufacturer=Keystone, Supplier Part Number 1=36-5000-ND
TP3 TP12: "Test Point, Miniature, Black, TH", Color=Black, Manufacturer=Keystone, Supplier Part Number 1=36-5001-ND
TP7 TP8 TP9 TP10: "Test Point, Miniature, Orange, TH", Color=Orange, Manufacturer=Keystone, Supplier Part Number 1=36-5003-ND
U1: library part CMP-0080028-1, "Octal, 16--Bit, SPI, Voltage Output DAC with Internal Reference, RTE0016D (WQFN-16)", Alternate Manufacturer="Texas Instruments", Alternate PartNumber=DAC80508ZRTER
U2 U5: "36-V, Precision, Rail-to-Rail Input/Output, Low Offset Voltage, Low Input Bias Current Op Amp with e-trim, DGK0008A (VSSOP-8)", Alternate Manufacturer="Texas Instruments", Alternate PartNumber=OPA2192IDGK
U3: "Single Output High PSRR LDO, 150 mA, Fixed 5 V Output, 2.5 to 6.5 V Input, with Low IQ, 6-pin WSON (DSE), -40 to 125 degC, Green (RoHS & no Sb/Br)", Alternate Manufacturer="Texas Instruments", Alternate PartNumber=Equivalent, Supplier Part Number 1=296-25447-2-ND
U4: "Single Output High PSRR LDO, 150 mA, Fixed 3.3 V Output, 2.5 to 6.5 V Input, with Low IQ, 6-pin WSON (DSE), -40 to 125 degC, Green (RoHS & no Sb/Br)", Alternate Manufacturer="Texas Instruments", Alternate PartNumber=Equivalent, Supplier Part Number 1=296-32543-2-ND
ZZ1: library part AssemblyNoteLabel, Alternate Manufacturer=-
ZZ2 ZZ3 ZZ4: library part AssemblyNote, Alternate Manufacturer=-

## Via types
v1: diameter 24, hole 12, Top Layer to Bottom Layer, tented both sides, 118 vias
v2: diameter 19.68, hole 7.87, Top Layer to Bottom Layer, 1 vias

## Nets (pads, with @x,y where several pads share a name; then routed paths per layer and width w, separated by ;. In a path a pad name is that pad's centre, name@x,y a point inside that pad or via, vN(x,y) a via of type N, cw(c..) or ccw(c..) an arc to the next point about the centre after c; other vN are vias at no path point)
+3V3D: C44.1 R31.1 TP13.1 U4.1 | length 114.1
  Top Layer w25: TP13.1@250,1750 260,1740 C44.1@360,1740
+5V0A: C33.1 C34.1 L2.2 Q1.1 Q1.2 Q1.5 Q1.6 Q2.1 Q2.2 Q2.5 Q2.6 R12.1 R13.1 R30.1
  other v1: 1298.03,846.99 1660,846.99 1298.03,889.99 1660,889.99 1298.03,929.99 1660,929.99 258,1226.99 258,1265.99 300,1265.99 1124.38,1274.24 1124.38,1313.24 1166.38,1313.24 1752,1736.99 1752,1774.99 1752,1809.15 938,1911.99 980,1911.99 980,1950.99
+5V0A_OUT: C32.1 L2.1 TP2.1 U3.1 | length 87.1
  Top Layer w20: C32.1@1589,1678.99 1605.41,1662.58 TP2.1@1605.41,1598.69
+6V5_IN: C29.1 C30.1 C41.1 D1.1 L1.1 L3.1 R29.1
  other v1: 607,1637 653,1637 695,1637 1153,1764 1201,1764.81 1153,1814 1201,1814.99 1153,1857 1202,1857
+6V5A: C31.1 L1.2 TP1.1 U3.4 U3.6 | length 211.7
  Top Layer w20: TP1.1@1202.78,1598.69 1323.7,1598.69 1349,1623.99 L1.2@1349,1678.99
+6V5A2: C42.1 L3.2 U4.4 U4.6
DAC_C\S\: R35.2 U1.12 | length 407.4
  Top Layer w8: R35.2@293.62,2100 645.99,2100 668.35,2077.64 U1.12@668.35,2054.27
DAC_CH0: R9.1 U1.2 | length 703.8
  Top Layer w8: R9.1@505.38,1438.99 505.38,1474.99 537.38,1506.99 652.82,1506.99 755,1609.17 755,1782.28 705,1832.28 705,1900.07 688.04,1917.03 U1.2@688.04,1944.03
DAC_CH1: R22.1 U1.3 | length 571.2
  Top Layer w8: R22.1@692.62,1438.99 692.62,1499.61 780,1586.99 780,1796.65 730.65,1845.99 730.65,1898.34 707.72,1921.27 U1.3@707.72,1944.03
DAC_CH2: R8.1 U1.4 | length 819.6
  Top Layer w8: U1.4@727.41,1944.03 727.41,1924.58 763,1888.99 763,1852.99 1177,1438.99 R8.1@1305.38,1438.99
DAC_CH3: R21.1 U1.5 | length 1034.6
  Top Layer w8: U1.5@753,1969.62 772.37,1969.62 783,1958.99 783,1865.99 1149,1499.99 1467,1499.99 1492.62,1474.37 R21.1@1492.62,1438.99
DAC_SCLK: R32.2 U1.13 | length 349.7
  Top Layer w8: R32.2@293.62,2030 588.68,2030 590,2028.68 U1.13@642.76,2028.68
DAC_SDI: R33.2 U1.14 | length 369.4
  Top Layer w8: R33.2@293.62,1960 375.01,1960 424,2008.99 U1.14@642.76,2008.99
DAC_SDO: R34.2 U1.15 | length 390.4
  Top Layer w8: R34.2@293.62,1889.64 340.65,1889.64 440.31,1989.31 U1.15@642.76,1989.31
DAC_VDD: C36.1 C37.1 R30.2 U1.7
DAC_VIO: C38.1 C39.1 R31.2 U1.16
GND: C3.2 C4.2 C5.2 C6.2 C7.2 C8.2 C9.2 C10.2 C11.2 C12.2 C13.2 C14.2 C15.2 C16.2 C19.2 C20.2 C21.2 C22.2 C23.2 C24.2 C25.2 C26.2 C27.2 C28.2 C29.2 C30.2 C31.2 C32.2 C33.2 C34.2 C35.2 C36.2 C37.2 C38.2 C39.2 C40.2 C41.2 C42.2 C43.2 C44.2 D2.1 J2.1 J3.2 J3.3 J3.4 J3.5 J5.2 J5.3 J5.4 J5.5 J7.2 J7.3 J7.4 J7.5 J9.2 J9.3 J9.4 J9.5 J11.2 R1.1 R4.1 R11.2 R14.1 R17.1 R24.2 R25.1 R26.1 R27.1 R28.1 TP3.1 TP12.1 U1.6 U1.17 U2.4 U3.2 U3.5 U4.2 U4.5 U5.4 | length 2494.7
  Top Layer w8: v1(396,1662) 396,1685.39 409.6,1698.99 U4.2@426.38,1698.99 U4.5@473.62,1698.99 ; C41.2@663.12,1739.31 C41.2@663.81,1740 ; C40.2@668.31,1829.69 C40.2@669,1828.99 ; v2(697.88,1999.15) 721.48,1999.15 731.32,1989.31 U1.6@753,1989.31 ; U3.5@1475.38,1698.99 U3.2@1522.62,1698.99 1545,1698.99 1558,1711.99 v1(1558,1714.99) ; R1.1@1498.31,1026.06 R1.1@1499,1025.37 ; C26.2@1698.31,1019.69 C26.2@1699,1018.99
  Top Layer w20: C41.2@663.81,1740 v1(701,1740) ; v1(669,1797.99) C40.2@669,1828.99 ; v1(1499,985.99) R1.1@1499,1025.37 ; v1(1699,987.99) C26.2@1699,1018.99
  Top Layer w25: J3.2@86,311.49 118.5,278.99 203.5,278.99 ; J3.3@86,586.49 118.5,618.99 203.5,618.99 ; 519,204.99 519,119.99 J5.3@551.5,87.49 ; J5.2@826.5,87.49 859,119.99 859,204.99 ; 1139,203.99 1139,118.99 J7.3@1171.5,86.49 ; J7.2@1446.5,86.49 1479,118.99 1479,203.99 ; 1793.36,278.99 1878.36,278.99 J9.3@1910.86,311.49 ; 1793.36,618.99 1878.36,618.99 J9.2@1910.86,586.49
  Bottom Layer w25: J3.4@86,311.49 118.5,278.99 203.5,278.99 ; J3.5@86,586.49 118.5,618.99 203.5,618.99 ; 519,204.99 519,119.99 J5.5@551.5,87.49 ; J5.4@826.5,87.49 859,119.99 859,204.99 ; 1139,203.99 1139,118.99 J7.5@1171.5,86.49 ; J7.4@1446.5,86.49 1479,118.99 1479,203.99 ; 1793.36,278.99 1878.36,278.99 J9.5@1910.86,311.49 ; 1793.36,618.99 1878.36,618.99 J9.4@1910.86,586.49
  other v1: 635,464.99 1352.62,471.99 635,504.99 1352,513.99 635,548.99 679,548.99 1302,559.99 1351,559.99 489,630.99 1538,632.99 461,661.99 499,661.99 537,661.99 1503,666.93 1538,666.99 1571,666.99 1595.94,720.8 1235.62,722.61 1631,748.99 1271,750.99 1368,766.99 1369,800.99 712,918.99 745,946.99 491,1016.99 841,1019.99 526,1045.37 812.62,1055.99 1122,1144.64 1122,1180.64 1122,1216.64 939,1241.99 354.65,1265.84 390.65,1265.84 426.65,1265.84 699,1272.99 911,1274.99 1500,1277.99 745,1287.99 1671,1311.99 462,1314.64 1536,1314.64 1262,1315.99 745,1329.99 1643,1344.99 462,1350.64 1536,1350.64 1262,1351.99 745,1371.99 462,1386.64 1536,1386.64 1262,1387.99 545,1606 360,1612 515,1620 324,1627 545,1644 1288,1646.99 1704,1646.99 1740,1646.99 361,1648 1255,1651.99 1231,1676.99 1439,1765.99 1590,1770.99 1408,1777.99 1618.37,1787.99 1589,1806.99 1408,1815.99 1442,1815.99 521,1857.99 561,1857.99 597,1857.99 812,1910.99 849,1910.99 885,1910.99 1267,1993.99 1267,2037.99
NetC1_1: C1.1 R3.1 | length 62.6
  Top Layer w8: C1.1@1319,1018.99 1372.62,1018.99 R3.1@1379,1025.37
NetC1_2: C1.2 R6.1 U5.7 | length 218.1
  Top Layer w8: R6.1@1260.34,1072.61 1266.72,1078.99 C1.2@1319,1078.99 1319,1093.99 1354,1128.99 1354,1173.35 1341.15,1186.2 U5.7@1311.4,1186.2
NetC2_1: C2.1 R4.2 R5.1 U2.6 | length 376.3
  Top Layer w8: U2.6@511.4,1212.79 595.2,1212.79 639.38,1168.61 639.38,1087.61 649,1077.99 C2.1@649,1068.99 R5.1@649,1002.61 R4.2@709,1002.61
NetC2_2: C2.2 R7.1 U2.7 | length 243.3
  Top Layer w8: U2.7@511.4,1187.2 556.8,1187.2 589,1154.99 C2.2@589,1068.99 R7.1@589,1002.61
NetC3_1: C3.1 C4.1 R8.2 U5.5 | length 243.1
  Top Layer w8: U5.5@1311.4,1237.38 1344,1237.38 1359,1252.38 C4.1@1359,1318.99 C3.1@1359,1380.34 1359,1432.61 R8.2@1352.62,1438.99
NetC5_1: C5.1 C6.1 R9.2 U2.5 | length 245.2
  Top Layer w8: U2.5@511.4,1238.38 549.39,1238.38 559,1247.99 C5.1@559,1318.99 C6.1@559,1378.99 559,1432.61 R9.2@552.62,1438.99
NetC17_1: C17.1 R16.1 | length 57.2
  Top Layer w8: R16.1@1632.62,1193.99 1638.69,1187.93 C17.1@1638.69,1139.31
NetC17_2: C17.2 R19.1 U5.1 | length 167.7
  Top Layer w8: U5.1@1486.6,1160.61 1527.71,1160.61 1549,1139.31 C17.2@1578.69,1139.31 1578.69,1072.93 R19.1@1579,1072.61
NetC18_1: C18.1 R17.2 R18.1 U2.2 | length 233.7
  Top Layer w8: U2.2@686.6,1187.2 777.2,1187.2 C18.1@779,1188.99 821,1188.99 831,1178.99 R18.1@855.38,1178.99 R17.2@855.38,1238.99
NetC18_2: C18.2 R20.1 U2.1 | length 186.4
  Top Layer w8: U2.1@686.6,1161.61 720.39,1161.61 753,1128.99 C18.2@779,1128.99 818,1128.99 828,1118.99 R20.1@855.38,1118.99
NetC19_1: C19.1 C20.1 R21.2 U5.3 | length 267
  Top Layer w8: R21.2@1445.38,1438.99 1439,1432.61 C20.1@1439,1378.99 C19.1@1439,1318.99 1439,1229.64 1456.85,1211.79 U5.3@1486.6,1211.79
NetC21_1: C21.1 C22.1 R22.2 U2.3 | length 267.6
  Top Layer w8: R22.2@645.38,1438.99 639,1432.61 C21.1@639,1378.99 C22.1@639,1318.99 639,1227.84 654.05,1212.79 U2.3@686.6,1212.79
NetC35_1: C35.1 U3.3 | length 63
  Top Layer w8: U3.3@1522.62,1718.68 1522.62,1742.61 1529,1748.99 C35.1@1529,1778.99
NetC43_1: C43.1 U4.3 | length 61.2
  Top Layer w8: C43.1@421.82,1620 421.82,1650.81 426.38,1655.38 U4.3@426.38,1679.31
NetD1_2: D1.2 J11.1
NetD2_2: D2.2 R29.2
NetJ4_2: J4.2 R25.2 | length 146.4
  Top Layer w8: J4.2@519,408.99 R25.2@519,555.37
NetJ6_2: J6.2 R26.2 | length 156.4
  Top Layer w8: R26.2@742.62,498.99 J6.2@899,498.99
NetJ8_2: J8.2 R27.2 | length 156.4
  Top Layer w8: J8.2@1099,498.99 R27.2@1255.38,498.99
NetJ10_2: J10.2 R28.2 | length 146.4
  Top Layer w8: J10.2@1509,408.99 R28.2@1509,555.37
NetQ1_3: Q1.3 R6.2 | length 142.2
  Top Layer w8: Q1.3@1181.6,936.24 1181.6,981.59 1225.38,1025.37 R6.2@1260.34,1025.37
NetQ1_4: Q1.4 R10.1 R11.1 | length 588.3
  Top Layer w8: Q1.4@1181.6,841.75 v1(1181.6,795.99) 1181.6,762.77 R11.1@1185.38,758.99 ; v1(1374.69,937.37) 1374.69,899.69 R10.1@1375.38,898.99
  Bottom Layer w8: v1(1181.6,795.99) 1181.6,983.59 1226,1027.99 1333,1027.99 1374.69,986.31 v1(1374.69,937.37)
NetQ2_3: Q2.3 R19.2 | length 105.1
  Top Layer w8: Q2.3@1543.57,936.24 1542,937.8 1542,988.37 R19.2@1579,1025.37
NetQ2_4: Q2.4 R23.1 R24.1 | length 390.6
  Top Layer w8: Q2.4@1543.57,841.75 v1(1543.57,793.99) 1543.57,759.31 R24.1@1545.69,757.18 ; R23.1@1639,1025.37 1640,1024.37 v1(1640,989.99)
  Bottom Layer w8: v1(1543.57,793.99) 1543.57,950.56 1583,989.99 v1(1640,989.99)
NetR1_2: R1.2 R2.1 R3.2 U5.6 | length 311.8
  Top Layer w8: U5.6@1311.4,1211.79 1353.41,1211.79 1379,1186.2 R3.2@1379,1072.61 R2.1@1439,1072.61 R1.2@1499,1072.61
NetR14_2: R14.2 R15.1 R16.2 U5.2 | length 217.8
  Top Layer w8: U5.2@1486.6,1186.2 1547.2,1186.2 1555,1193.99 R16.2@1585.38,1193.99 R15.1@1585.38,1251.02 1585.38,1306.99 R14.2@1587.38,1308.99
NetTP7_1: TP7.1 U1.8 | length 541.2
  Top Layer w8: U1.8@753,2028.68 776.68,2028.68 827,2078.99 1023,2078.99 TP7.1@1200,2255.99
NetTP8_1: TP8.1 U1.9 | length 426.1
  Top Layer w8: U1.9@727.41,2054.27 727.41,2081.4 759,2112.99 913.99,2112.99 1050,2249 TP8.1@1050,2255.99
NetTP9_1: TP9.1 U1.10 | length 299.6
  Top Layer w8: U1.10@707.72,2054.27 707.72,2096.72 785,2174 824.01,2174 TP9.1@901,2250.99
NetTP10_1: TP10.1 U1.11 | length 222.4
  Top Layer w8: U1.11@688.04,2054.27 688.04,2122.04 750,2184 TP10.1@750,2250.99
OPA_VCC1: C13.1 C14.1 R12.2 U2.8
OPA_VCC2: C15.1 C16.1 R13.2 U5.8
REF_DAC: C40.1 U1.1 | length 55.3
  Top Layer w8: U1.1@668.35,1944.03 668.35,1889.64 C40.1@669,1888.99
SPI_C\S\: J1.8 R35.1 TP11.1 | length 1010.6
  Top Layer w8: J1.8@99,1364.81 163.69,1364.81 250,1451.13 TP11.1@250,1600 ; v1(246,2137) 246,2110.99 240,2104.99 245.69,2099.31 R35.1@246.38,2100
  Bottom Layer w8: v1(246,2137) 284,2099 284,1909 172,1797 172,1678 TP11.1@250,1600
SPI_CLK: J1.6 R32.1 TP4.1 | length 814.2
  Top Layer w8: v1(208,2029.31) 245.69,2029.31 R32.1@246.38,2030
  Bottom Layer w8: J1.6@99,1564.81 150,1615.81 150,1816 240,1906 240,1997.31 v1(208,2029.31) 208,2208.24 TP4.1@250.76,2250.99
SPI_SIMO: J1.4 R33.1 TP5.1 | length 865.6
  Top Layer w8: v1(208,1959.31) 245.69,1959.31 R33.1@246.38,1960
  Bottom Layer w8: J1.4@99,1764.81 99,1801 208,1910 v1(208,1959.31) 180,1987.31 180,2262 238,2320 330,2320 TP5.1@400,2250
SPI_SOMI: J1.3 R34.1 TP6.1 | length 1076.1
  Top Layer w8: J1.3@99,1864.81 123.82,1889.64 R34.1@246.38,1889.64
  Bottom Layer w8: J1.3@99,1864.81 160,1925.81 160,2310 200,2350 450,2350 TP6.1@550,2250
